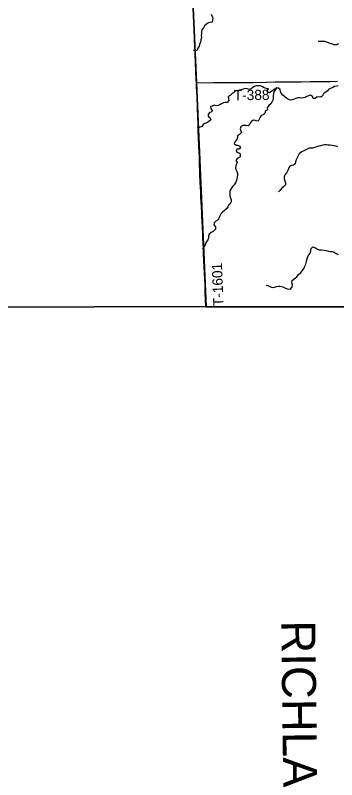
# Model space of a CAD drawing. Extents: x 1874609 to 2204689, y 815661 to 1281160.
# Drawn here: x 1981449 to 1990885, y 1076369 to 1098814 of the extents above; entities that cross this region are included whole.
import ezdxf

# ---------------------------------------------------------------- set-up
doc = ezdxf.new("R2010")
doc.units = 0
for name, color, linetype in [('GM_X_Adjacent_County', 7, 'Continuous'), ('GM_X_Adjacent_County_Text', 7, 'Continuous'), ('GM_X_County', 7, 'Continuous'), ('GM_X_County_Road', 7, 'Continuous'), ('GM_X_Minor_River', 7, 'Continuous'), ('GM_X_Township', 7, 'Continuous'), ('GM_X_Township_Road', 7, 'Continuous'), ('GM_X_Township_Road_Text', 7, 'Continuous')]:
    doc.layers.add(name, color=color, linetype=linetype)

msp = doc.modelspace()

# ---------------------------------------------------------------- linework, layer by layer
at = {"layer": 'GM_X_Adjacent_County'}
for points in [[(2013201, 1130286), (2013424, 1120950), (2013523, 1116786), (2010804, 1116774), (2007584, 1116766), (2002726, 1116787), (1997008, 1116752), (1993289, 1116726), (1991389, 1116703), (1985906, 1116658), (1986118, 1111481), (1986158, 1110698), (1986177, 1110266), (1986179, 1110020), (1986478, 1103440), (1986770, 1096835), (1987050, 1090265), (1980483, 1090246)], [(1980483, 1090246), (1987050, 1090265), (1989481, 1090257), (1991142, 1090253), (1991169, 1087990), (1991292, 1083651), (1991341, 1081115), (1991355, 1080412), (1991419, 1075774)]]:
    msp.add_lwpolyline(points, dxfattribs=at)
at = {"layer": 'GM_X_County'}
msp.add_lwpolyline([(1991419, 1075774), (1991355, 1080412), (1991341, 1081115), (1991292, 1083651), (1991169, 1087990), (1991142, 1090253), (1989481, 1090257), (1987050, 1090265), (1986770, 1096835), (1986478, 1103440)], dxfattribs=at)
at = {"layer": 'GM_X_County_Road'}
for points in [[(1987043, 1090256), (1987096, 1090256), (1987126, 1090256), (1987158, 1090256), (1987328, 1090256), (1988117, 1090253), (1988462, 1090252), (1988643, 1090252), (1988807, 1090252), (1989185, 1090251), (1989480, 1090253)], [(1989480, 1090253), (1989531, 1090253), (1989810, 1090251), (1990155, 1090252), (1990664, 1090249), (1991142, 1090245)]]:
    msp.add_lwpolyline(points, dxfattribs=at)
at = {"layer": 'GM_X_Minor_River'}
for points in [[(1987185, 1098838), (1987231, 1098786), (1987253, 1098728), (1987243, 1098676), (1987226, 1098616), (1987174, 1098602), (1987120, 1098596), (1987062, 1098554), (1987004, 1098501), (1986970, 1098447), (1986925, 1098387), (1986919, 1098333), (1986915, 1098281), (1986903, 1098221), (1986912, 1098163), (1986896, 1098097), (1986882, 1098028), (1986858, 1097961), (1986847, 1097908), (1986809, 1097851), (1986785, 1097789), (1986735, 1097771), (1986684, 1097792)], [(1990942, 1097972), (1990882, 1097948), (1990814, 1097946), (1990760, 1097963), (1990664, 1097999), (1990598, 1098023), (1990538, 1098040), (1990460, 1098042), (1990404, 1098048), (1990346, 1098047), (1990342, 1098045)], [(1989126, 1096680), (1989070, 1096649), (1989020, 1096613), (1988970, 1096581), (1988917, 1096541), (1988855, 1096548), (1988844, 1096598), (1988878, 1096652), (1988822, 1096666), (1988760, 1096688), (1988708, 1096710), (1988648, 1096739), (1988582, 1096743), (1988530, 1096739), (1988472, 1096720), (1988420, 1096694), (1988370, 1096658), (1988314, 1096638), (1988260, 1096650), (1988192, 1096661), (1988138, 1096643), (1988080, 1096625), (1988028, 1096617), (1987978, 1096608), (1987918, 1096592), (1987867, 1096550), (1987805, 1096508), (1987753, 1096456), (1987701, 1096425), (1987707, 1096361), (1987716, 1096308), (1987672, 1096257), (1987616, 1096257), (1987560, 1096243), (1987504, 1096217), (1987452, 1096186), (1987402, 1096166), (1987346, 1096156), (1987284, 1096176), (1987230, 1096146), (1987180, 1096137), (1987185, 1096081), (1987231, 1096018), (1987209, 1095966), (1987153, 1095963), (1987110, 1095901), (1987116, 1095849), (1987172, 1095806), (1987186, 1095744), (1987134, 1095694), (1987077, 1095659), (1987015, 1095639), (1986963, 1095607), (1986921, 1095549), (1986784, 1095501)], [(1989126, 1096680), (1989038, 1096569), (1989033, 1096515), (1989023, 1096451), (1989023, 1096395), (1989021, 1096341), (1988988, 1096281), (1988948, 1096217), (1988890, 1096165), (1988841, 1096101), (1988855, 1096039), (1988797, 1096007), (1988773, 1095943), (1988729, 1095891), (1988666, 1095874), (1988638, 1095818), (1988610, 1095762), (1988576, 1095702), (1988524, 1095710), (1988464, 1095734), (1988406, 1095729), (1988356, 1095669), (1988333, 1095615), (1988283, 1095567), (1988231, 1095575), (1988179, 1095577), (1988127, 1095574), (1988073, 1095540), (1988049, 1095482), (1988066, 1095424), (1988090, 1095370), (1988036, 1095312), (1987972, 1095276), (1987968, 1095222), (1987955, 1095166), (1987909, 1095110), (1987875, 1095046), (1987929, 1095004), (1987985, 1094998), (1988040, 1094971), (1988062, 1094917), (1988008, 1094885), (1987950, 1094880), (1987932, 1094820), (1987986, 1094785), (1988038, 1094763), (1988055, 1094713), (1988049, 1094661), (1987967, 1094607), (1987925, 1094555), (1987960, 1094505), (1987946, 1094453), (1987920, 1094395), (1987914, 1094339), (1987927, 1094287), (1987949, 1094231), (1987975, 1094173), (1987977, 1094120), (1987964, 1094068), (1987958, 1094006), (1987932, 1093946), (1987918, 1093894), (1987879, 1093833), (1987827, 1093787), (1987775, 1093707), (1987747, 1093655), (1987744, 1093583), (1987752, 1093511), (1987764, 1093457), (1987785, 1093398), (1987789, 1093334), (1987759, 1093282), (1987709, 1093239), (1987689, 1093187), (1987648, 1093127), (1987584, 1093071), (1987534, 1093029), (1987484, 1092989), (1987401, 1092812)], [(1990926, 1096744), (1990876, 1096735), (1990822, 1096723), (1990770, 1096689), (1990708, 1096669), (1990654, 1096641), (1990606, 1096586), (1990556, 1096552), (1990501, 1096506), (1990473, 1096452), (1990417, 1096412), (1990359, 1096416), (1990303, 1096405), (1990251, 1096375), (1990199, 1096373), (1990177, 1096429), (1990115, 1096472), (1990059, 1096448), (1990009, 1096428), (1989959, 1096404), (1989907, 1096387), (1989853, 1096377), (1989801, 1096391), (1989737, 1096393), (1989685, 1096374), (1989635, 1096354), (1989579, 1096336), (1989522, 1096326), (1989471, 1096344), (1989415, 1096385), (1989363, 1096417), (1989307, 1096473), (1989253, 1096526), (1989234, 1096580), (1989230, 1096638), (1989178, 1096678), (1989126, 1096680)], [(1990920, 1094948), (1990867, 1094968), (1990811, 1094981), (1990749, 1094991), (1990689, 1094997), (1990635, 1094999), (1990583, 1095006), (1990527, 1095008), (1990475, 1094996), (1990419, 1094984), (1990365, 1094973), (1990298, 1094947), (1990236, 1094927), (1990186, 1094913), (1990134, 1094916), (1990078, 1094914), (1990018, 1094882), (1989956, 1094852), (1989900, 1094827), (1989838, 1094793), (1989780, 1094749), (1989749, 1094691), (1989725, 1094625), (1989699, 1094565), (1989680, 1094509), (1989664, 1094451), (1989612, 1094413), (1989558, 1094402), (1989500, 1094374), (1989466, 1094310), (1989451, 1094256), (1989423, 1094198), (1989367, 1094132), (1989343, 1094072), (1989338, 1094022), (1989358, 1093956), (1989380, 1093896), (1989379, 1093838), (1989331, 1093786), (1989273, 1093738), (1989219, 1093672), (1989181, 1093630)], [(1987401, 1092812), (1987337, 1092766), (1987287, 1092716), (1987277, 1092666), (1987329, 1092600), (1987325, 1092530), (1987255, 1092468), (1987195, 1092432), (1987142, 1092390), (1987126, 1092338), (1987120, 1092284), (1987090, 1092200), (1987056, 1092150), (1987030, 1092089), (1986944, 1091948)], [(1988812, 1090888), (1988864, 1090878), (1988944, 1090836), (1989002, 1090826), (1989060, 1090832), (1989122, 1090848), (1989174, 1090862), (1989228, 1090862), (1989299, 1090844), (1989379, 1090804), (1989429, 1090778), (1989527, 1090768), (1989577, 1090840), (1989585, 1090900), (1989567, 1090958), (1989575, 1091030), (1989641, 1091078), (1989711, 1091132), (1989753, 1091194), (1989835, 1091264), (1989884, 1091318), (1989916, 1091376), (1989938, 1091432), (1989976, 1091503), (1990002, 1091581), (1990012, 1091633), (1990030, 1091699), (1990044, 1091753), (1990102, 1091833), (1990122, 1091899), (1990134, 1091963), (1990180, 1092015), (1990246, 1091993), (1990306, 1091953), (1990374, 1091927), (1990441, 1091923), (1990515, 1091919), (1990579, 1091903), (1990641, 1091885), (1990703, 1091883), (1990753, 1091881), (1990813, 1091859), (1990865, 1091819), (1990927, 1091787)]]:
    msp.add_lwpolyline(points, dxfattribs=at)
at = {"layer": 'GM_X_Township'}
msp.add_lwpolyline([(2013829, 1103586), (2013944, 1098634), (2014137, 1090288), (2012641, 1090280), (2012470, 1090289), (2009774, 1090285), (2008657, 1090282), (2003388, 1090262), (2003317, 1090262), (1999821, 1090248), (1997562, 1090254), (1997016, 1090252), (1996192, 1090258), (1991142, 1090253), (1989481, 1090257), (1987050, 1090265), (1986770, 1096835), (1986478, 1103440)], dxfattribs=at)
at = {"layer": 'GM_X_Township_Road'}
for points in [[(1986766, 1096836), (1986762, 1096919), (1986750, 1097182), (1986741, 1097395), (1986729, 1097706), (1986720, 1097936), (1986714, 1098084), (1986707, 1098231), (1986703, 1098329), (1986697, 1098477), (1986690, 1098641), (1986685, 1098772), (1986677, 1098936)], [(1986766, 1096836), (1987042, 1096835), (1987255, 1096836), (1987518, 1096838), (1987649, 1096838), (1987784, 1096836), (1987968, 1096836), (1988107, 1096838), (1988419, 1096845), (1988829, 1096851), (1989075, 1096858), (1989256, 1096862), (1989370, 1096861), (1989633, 1096857), (1989830, 1096859), (1990108, 1096866), (1990274, 1096868), (1990412, 1096865), (1990543, 1096866), (1990698, 1096872), (1990911, 1096876)], [(1987043, 1090256), (1987043, 1090314), (1987038, 1090405), (1987028, 1090713), (1987020, 1090910), (1987014, 1091074), (1987005, 1091244), (1986996, 1091414), (1986986, 1091614), (1986978, 1091811), (1986970, 1091975), (1986965, 1092122), (1986959, 1092276), (1986954, 1092417), (1986944, 1092597), (1986936, 1092761), (1986927, 1092907), (1986922, 1093002), (1986913, 1093203), (1986907, 1093318), (1986899, 1093498), (1986893, 1093613), (1986886, 1093776), (1986880, 1093908), (1986878, 1093957), (1986871, 1094104), (1986868, 1094219), (1986862, 1094448), (1986855, 1094629), (1986854, 1094644), (1986848, 1094792), (1986840, 1094956), (1986835, 1095038), (1986828, 1095153), (1986823, 1095267), (1986820, 1095365), (1986818, 1095464), (1986816, 1095562), (1986815, 1095644), (1986809, 1095806), (1986804, 1095907), (1986802, 1096021), (1986798, 1096168), (1986788, 1096398), (1986779, 1096573), (1986772, 1096725), (1986766, 1096836)]]:
    msp.add_lwpolyline(points, dxfattribs=at)

# ---------------------------------------------------------------- texts
at = {"layer": 'GM_X_Adjacent_County_Text'}
msp.add_text('RICHLAND COUNTY', height=1000, rotation=270.71, dxfattribs=at).set_placement((1989255, 1081041))
at = {"layer": 'GM_X_Township_Road_Text'}
for s, rotation, p in [('T-388', 0.8381, (1987866, 1096317)), ('T-1601', 92.0784, (1987563, 1090280))]:
    msp.add_text(s, height=300, rotation=rotation, dxfattribs=at).set_placement(p)

doc.saveas('drawing.dxf')
